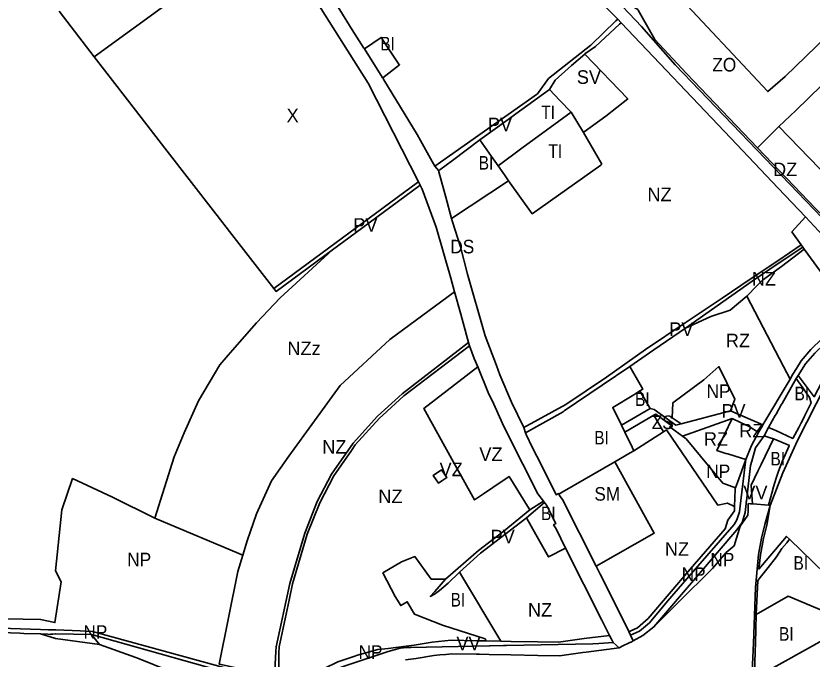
# Model space of a CAD drawing. Extents: x -650451 to -642268, y -1075216 to -1066610.
# Drawn here: x -647439 to -646558, y -1073034 to -1072322 of the extents above; entities that cross this region are included whole.
import ezdxf

# ---------------------------------------------------------------- set-up
doc = ezdxf.new("R2010")
doc.units = 0
doc.header["$LTSCALE"] = 6
doc.layers.add('1', color=7, linetype='Continuous', lineweight=35)
doc.layers.add('2', color=7, linetype='Continuous')
doc.layers.add('3', color=7, linetype='Continuous')

msp = doc.modelspace()

# ---------------------------------------------------------------- linework, layer by layer
at = {"layer": '1'}
for p, q in [((-647351.86, -1072367.52), (-647265.794, -1072304.439)), ((-647351.86, -1072367.52), (-647390.58, -1072316.75)), ((-646772.7, -1072325.66), (-646768.87, -1072329.6)), ((-646810.77, -1072451.09), (-646824.42, -1072428.58)), ((-646970.58, -1072493.62), (-646975.12, -1072488.48)), ((-646893.64, -1072504.45), (-646956.61, -1072546.07)), ((-646993.05, -1072505.68), (-646991.24, -1072509.24)), ((-646493.229, -1072622.74), (-646564.91, -1072544.37)), ((-646569.69, -1072575.19), (-646567.89, -1072577.87)), ((-646566.49, -1072579.96), (-646567.89, -1072577.87)), ((-646937.98, -1072683.25), (-646936.6, -1072687.07)), ((-646612.11, -1072774.56), (-646581.92, -1072723.91)), ((-646575.17, -1072723.31), (-646573.04, -1072719.85)), ((-646647.93, -1072759.01), (-646702.45, -1072773.39)), ((-646612.11, -1072774.56), (-646647.93, -1072759.01)), ((-646646.12, -1072767.32), (-646701.12, -1072787.08)), ((-646876.53, -1072777.33), (-646874.79, -1072783.28)), ((-646768.74, -1072774.78), (-646765, -1072782.52)), ((-646873.71, -1072877.54), (-646853.76, -1072860.47)), ((-646603.99, -1072863.84), (-646606.09, -1072863.23)), ((-646947.88, -1072937.51), (-646902.136, -1073013.834)), ((-647346.22, -1073017.52), (-647354.76, -1073006.65)), ((-646918.156, -1073013.511), (-646902.136, -1073013.834))]:
    msp.add_line(p, q, dxfattribs=at)
for points in [[(-646518.208, -1072321.92), (-646587.666, -1072389.082), (-646606.848, -1072405.785), (-646712.634, -1072292.59), (-646555.051, -1072174.933)], [(-646772.7, -1072325.66), (-646800.24, -1072297.4), (-646825.7, -1072283.54), (-646836.27, -1072271.9), (-646847.85, -1072247.99), (-646866.7, -1072227.81), (-646875, -1072218.53), (-646884.58, -1072207.83), (-646896.524, -1072194.888)], [(-646882.135, -1072193.308), (-646874.21, -1072201.34), (-646837.4, -1072236.27), (-646814.33, -1072251.34), (-646806.14, -1072261.22), (-646794.77, -1072282.59), (-646746.37, -1072333.94), (-646709.19, -1072376.06), (-646555.4, -1072536.38), (-646499.98, -1072594.11), (-646469.93, -1072603.28), (-646479.13, -1072616.26), (-646470.33, -1072617.33), (-646466.84, -1072620.18)], [(-646875.509, -1072192.58), (-646870.21, -1072199.51), (-646833.75, -1072233.32), (-646803.98, -1072254.74), (-646791.59, -1072279.78), (-646769.24, -1072303.65), (-646750.58, -1072315.02), (-646750.12, -1072315.82), (-646731.82, -1072348.2), (-646696.83, -1072385.81), (-646618.158, -1072468.098)], [(-647109.813, -1072268.588), (-647080.27, -1072315.34), (-647066.38, -1072337.31), (-647053.45, -1072357.77), (-647052.94, -1072358.64)], [(-647123.774, -1072277.899), (-647048.91, -1072396.46), (-646993.05, -1072505.68)], [(-646772.7, -1072325.66), (-646774.73, -1072327.6), (-646802.59, -1072354.28), (-646849.19, -1072391.28), (-646861.68, -1072408.1), (-646910.02, -1072442.61), (-646975.12, -1072488.48)], [(-646768.87, -1072329.6), (-646770.77, -1072331.34), (-646797.51, -1072355.77), (-646809.18, -1072364.18), (-646809.315, -1072364.299)], [(-646564.91, -1072544.37), (-646595.21, -1072512.47), (-646647.48, -1072457.43), (-646768.87, -1072329.6)], [(-647052.94, -1072358.64), (-647034.39, -1072345.9), (-647027.28, -1072356.56), (-647022.12, -1072364.32), (-647014.73, -1072375.41), (-647014.14, -1072376.08), (-647032.76, -1072390.75)], [(-647052.94, -1072358.64), (-647035.2, -1072386.94), (-647033.83, -1072389.07), (-647033.19, -1072390.06), (-647032.76, -1072390.75)], [(-646504.244, -1072357.026), (-646575.792, -1072426.789), (-646594.561, -1072444.38)], [(-647153.2, -1072623.68), (-647202.22, -1072560.47), (-647215.71, -1072543.07), (-647217.32, -1072540.99), (-647273.75, -1072468.22), (-647306.23, -1072426.35), (-647351.86, -1072367.52)], [(-646848.37, -1072403.6), (-646841.82, -1072393.03), (-646827.49, -1072380.37), (-646823.75, -1072377.06), (-646809.315, -1072364.299)], [(-646809.315, -1072364.299), (-646761.676, -1072413.971), (-646785.86, -1072433.01), (-646809.96, -1072450.5), (-646810.77, -1072451.09)], [(-647032.76, -1072390.75), (-647031.38, -1072392.97), (-646994.61, -1072453.36), (-646978.14, -1072483.05), (-646975.12, -1072488.48)], [(-646848.37, -1072403.6), (-646885.4, -1072430.37), (-646893.97, -1072436.54), (-646925.22, -1072459.03)], [(-646848.37, -1072403.6), (-646836.67, -1072415.8), (-646824.42, -1072428.58)], [(-646824.42, -1072428.58), (-646878.91, -1072468.54), (-646905.18, -1072487.8)], [(-646893.64, -1072504.45), (-646867.283, -1072540.984), (-646791.569, -1072487.198), (-646790.354, -1072486.136), (-646810.77, -1072451.09)], [(-646594.561, -1072444.38), (-646594.606, -1072444.422), (-646618.158, -1072468.098)], [(-646345.741, -1072460.38), (-646389.081, -1072507.297), (-646445.877, -1072566.771), (-646459.575, -1072583.748), (-646594.561, -1072444.38)], [(-646970.58, -1072493.62), (-646969.66, -1072492.47), (-646955.66, -1072482.12), (-646925.22, -1072459.03)], [(-646905.18, -1072487.8), (-646912.22, -1072477.69), (-646925.22, -1072459.03)], [(-646464.22, -1072595.84), (-646496.37, -1072590.65), (-646554.1, -1072535.1), (-646618.158, -1072468.098)], [(-646970.58, -1072493.62), (-646970.68, -1072494.71), (-646962.95, -1072522.46), (-646956.61, -1072546.07)], [(-646905.18, -1072487.8), (-646898.1, -1072498.02), (-646893.64, -1072504.45)], [(-647153.2, -1072623.68), (-646994.2, -1072506.52), (-646993.05, -1072505.68)], [(-646991.24, -1072509.24), (-647063.38, -1072562.42), (-647088.4, -1072580.868)], [(-646953.2, -1072627.45), (-646957.5, -1072612.09), (-646973.68, -1072555.68), (-646989.01, -1072513.62), (-646991.24, -1072509.24)], [(-646956.61, -1072546.07), (-646955.57, -1072549.93), (-646946.68, -1072577.5), (-646939.01, -1072607.91), (-646920.3, -1072673.54), (-646919.57, -1072676.08), (-646907.04, -1072708.96), (-646903.17, -1072719.13), (-646890.36, -1072749.26), (-646876.53, -1072777.33)], [(-646569.69, -1072575.19), (-646580.06, -1072561.09), (-646564.91, -1072544.37)], [(-646876.53, -1072777.33), (-646830.21, -1072751.9), (-646785.3, -1072721.58), (-646742.12, -1072691.26), (-646698.27, -1072661.58), (-646657.13, -1072634.3), (-646626.37, -1072613.4), (-646595.77, -1072593.16), (-646569.69, -1072575.19)], [(-647284.75, -1072877.79), (-647263.58, -1072809.97), (-647252.29, -1072783.24), (-647236.54, -1072748.09), (-647212.92, -1072708.05), (-647198.77, -1072691.71), (-647172.36, -1072661.69), (-647146.21, -1072634.02), (-647088.4, -1072580.868)], [(-647088.4, -1072580.868), (-647150.75, -1072626.84), (-647153.2, -1072623.68)], [(-646567.89, -1072577.87), (-646594.18, -1072595.26), (-646623.97, -1072615.59), (-646697.89, -1072667.65)], [(-646629.86, -1072632.07), (-646618.94, -1072620.88), (-646612.66, -1072614.57), (-646591.49, -1072599.19), (-646566.49, -1072579.96)], [(-646566.49, -1072579.96), (-646534.36, -1072624), (-646531.13, -1072626.73), (-646513.209, -1072641.935)], [(-647187.445, -1072918.804), (-647182.61, -1072902.92), (-647172.48, -1072872.92), (-647155.72, -1072836.46), (-647136.69, -1072808.98), (-647079.74, -1072731.1), (-647025.04, -1072679.96), (-646953.2, -1072627.45)], [(-646937.98, -1072683.25), (-646943.62, -1072661.69), (-646946.31, -1072652.08), (-646953.2, -1072627.45)], [(-646629.86, -1072632.07), (-646648.27, -1072647.48), (-646669.6, -1072654.53), (-646697.89, -1072667.65)], [(-646629.86, -1072632.07), (-646589.37, -1072709.83), (-646581.92, -1072723.91)], [(-646486.95, -1072644.87), (-646523.5, -1072692.86), (-646553.12, -1072751.12), (-646573.72, -1072791.74), (-646590.21, -1072827.45), (-646603.99, -1072863.84)], [(-646581.92, -1072723.91), (-646578.98, -1072718.36), (-646575.12, -1072712.2), (-646569.81, -1072703.71), (-646558.97, -1072691.01), (-646534.18, -1072666.63), (-646517.19, -1072650.7), (-646512.21, -1072646.18), (-646511.84, -1072645.84), (-646510.28, -1072644.42)], [(-646573.04, -1072719.85), (-646565.04, -1072706.87), (-646554.85, -1072695.37), (-646544.26, -1072685.38), (-646538.05, -1072679.53), (-646531.95, -1072673.77), (-646519.93, -1072662.47)], [(-646697.89, -1072667.65), (-646732.95, -1072691.68), (-646759.491, -1072709.878)], [(-646573.04, -1072719.85), (-646555.29, -1072743.47), (-646527.32, -1072689.94), (-646522.77, -1072683), (-646513.05, -1072668.97)], [(-647152.621, -1073052.925), (-647150.83, -1073025.11), (-647150.52, -1073020.25), (-647135.42, -1072949.98), (-647118.99, -1072894.49), (-647105.33, -1072859.4), (-647089.44, -1072829.16), (-647065.33, -1072794.77), (-647038.45, -1072764.87), (-647011.27, -1072740.1), (-646937.98, -1072683.25)], [(-646936.6, -1072687.07), (-647009.34, -1072742.3), (-647032.7, -1072763.68), (-647036.29, -1072766.96), (-647063.04, -1072796.74), (-647067.22, -1072802.77), (-647086.65, -1072830.76), (-647102.38, -1072860.7), (-647116.33, -1072895.3), (-647132.47, -1072950.4), (-647136.39, -1072968.63), (-647147.48, -1073020.28), (-647147.55, -1073026.8), (-647147.6, -1073031.71), (-647147.85, -1073054.204)], [(-646936.6, -1072687.07), (-646931.52, -1072701.11), (-646927.67, -1072710.45)], [(-646869.88, -1072868.45), (-646870.73, -1072867.3), (-646893, -1072831.51), (-646910.92, -1072843.76), (-646921.07, -1072850.69), (-646931.1, -1072857.55), (-646954.51, -1072815.63), (-646987.154, -1072756.377), (-646927.67, -1072710.45)], [(-646854.98, -1072858.89), (-646861.08, -1072851.02), (-646877.79, -1072818.08), (-646892.15, -1072789.78), (-646900.09, -1072772.84), (-646909.9, -1072751.79), (-646916.01, -1072738.71), (-646927.67, -1072710.45)], [(-646759.491, -1072709.878), (-646789.83, -1072730.68), (-646831.91, -1072759.13), (-646833.27, -1072760.04), (-646874.79, -1072783.28)], [(-646759.491, -1072709.878), (-646747.87, -1072729.85), (-646744.94, -1072734.88), (-646748.3, -1072737.01)], [(-646647.93, -1072759.01), (-646643.36, -1072746.04), (-646660.89, -1072709.97), (-646677.39, -1072724.85), (-646711.79, -1072750.02), (-646712.46, -1072766.76), (-646702.45, -1072773.39)], [(-646575.17, -1072723.31), (-646572.64, -1072726.97), (-646570.64, -1072729.84), (-646560.74, -1072744.12), (-646558.8, -1072750.3), (-646566, -1072764.9), (-646567.66, -1072768.09), (-646569.72, -1072772.24), (-646572.45, -1072777.28), (-646579.08, -1072789.5), (-646598.02, -1072780.93), (-646599.75, -1072780.14), (-646605.93, -1072777.31)], [(-646575.17, -1072723.31), (-646590.83, -1072750.81), (-646591.82, -1072752.54), (-646597.52, -1072762.54), (-646598.51, -1072764.27), (-646601.72, -1072769.92), (-646605.93, -1072777.31)], [(-646768.74, -1072774.78), (-646778.2, -1072755.19), (-646755.1, -1072741.28), (-646748.3, -1072737.01)], [(-646748.3, -1072737.01), (-646737.05, -1072756.4), (-646768.74, -1072774.78)], [(-646702.45, -1072773.39), (-646708.65, -1072775.02), (-646732.5, -1072757.63), (-646737.05, -1072756.4)], [(-646754.96, -1072803.29), (-646722.072, -1072782.236), (-646732.76, -1072763.81), (-646765, -1072782.52)], [(-646732.76, -1072763.81), (-646730.73, -1072762.64), (-646712.35, -1072776), (-646715.23, -1072776.76), (-646709.14, -1072781.21), (-646701.12, -1072787.08)], [(-646631.08, -1072812.68), (-646643.01, -1072809.08), (-646651.11, -1072806.64), (-646653.02, -1072806.07), (-646663.07, -1072803.04), (-646646.12, -1072767.32)], [(-646646.12, -1072767.32), (-646636.84, -1072771.74), (-646627.38, -1072776.23), (-646616.97, -1072782.9)], [(-646616.97, -1072782.9), (-646616.6, -1072782.31), (-646612.76, -1072775.67), (-646612.4, -1072775.05), (-646612.11, -1072774.56)], [(-646610.86, -1072786.74), (-646606.795, -1072778.965), (-646606.54, -1072778.47), (-646605.93, -1072777.31)], [(-646874.79, -1072783.28), (-646874.23, -1072785.2), (-646866.86, -1072800.03), (-646857.61, -1072818.4), (-646840.87, -1072851.94), (-646838.22, -1072850.53), (-646837.81, -1072851.3)], [(-646765, -1072782.52), (-646756.92, -1072799.26), (-646754.96, -1072803.29)], [(-646732.95, -1072998.07), (-646684.36, -1072941.43), (-646640.96, -1072890.83), (-646635.11, -1072882.47), (-646631.89, -1072871.33), (-646630.76, -1072861.61), (-646630.57, -1072859.99), (-646630.45, -1072858.93), (-646625.91, -1072819.66), (-646624.54, -1072814.52), (-646620.27, -1072799.95), (-646610.86, -1072786.74)], [(-646722.072, -1072782.236), (-646722.07, -1072782.24), (-646718.72, -1072780.09), (-646662.12, -1072863.28), (-646651.42, -1072861.1), (-646643.445, -1072864.732)], [(-646631.08, -1072812.68), (-646624.81, -1072797.42), (-646616.97, -1072782.9)], [(-646600.37, -1072790.04), (-646603.99, -1072788.9), (-646610.86, -1072786.74)], [(-646642.404, -1072844.195), (-646656.36, -1072839.08), (-646697.09, -1072790.03), (-646701.12, -1072787.08)], [(-646623.67, -1072862.03), (-646623.71, -1072861.37), (-646623.95, -1072857.6), (-646625.02, -1072841.21), (-646617.596, -1072825.798), (-646614.07, -1072818.47), (-646600.37, -1072790.04)], [(-646600.37, -1072790.04), (-646599.44, -1072790.33), (-646582.77, -1072797.45), (-646582.98, -1072797.91), (-646590.47, -1072814.45), (-646594.89, -1072825.68), (-646597.38, -1072833.61), (-646600.35, -1072843.05), (-646602.37, -1072849.93), (-646605.32, -1072860.63), (-646606.09, -1072863.23)], [(-646754.96, -1072803.29), (-646758.9, -1072805.56), (-646775.85, -1072815.39)], [(-646631.08, -1072812.68), (-646631.85, -1072818.45), (-646637.52, -1072867.43), (-646637.92, -1072870.91), (-646640.92, -1072879.6), (-646644.12, -1072884.84), (-646689.13, -1072936.62), (-646717.7, -1072969.5), (-646737.7, -1072993.52), (-646748.51, -1073002.74), (-646758.44, -1073007.19)], [(-646631.08, -1072812.68), (-646640.313, -1072838.394), (-646642.404, -1072844.195)], [(-646775.85, -1072815.39), (-646834.08, -1072849.15), (-646837.81, -1072851.3)], [(-646775.85, -1072815.39), (-646732.28, -1072894.29), (-646796.68, -1072930.92)], [(-648023.818, -1072955.949), (-648023.495, -1072955.875), (-647811.752, -1072979.4), (-647778.296, -1072982.767), (-647411.293, -1072989.813), (-647395.47, -1072993.25), (-647388.62, -1072948.03), (-647394.87, -1072936.08), (-647387.64, -1072868.69), (-647375.92, -1072833.99), (-647331.82, -1072854.49), (-647284.75, -1072877.79)], [(-646642.404, -1072844.195), (-646642.39, -1072844.2), (-646642.438, -1072844.29), (-646642.939, -1072845.68), (-646643.445, -1072864.732)], [(-646837.81, -1072851.3), (-646836.5, -1072853.76), (-646833.67, -1072857.15), (-646796.68, -1072930.92)], [(-646853.76, -1072860.47), (-646854.98, -1072858.89), (-646869.88, -1072868.45)], [(-646853.76, -1072860.47), (-646851.49, -1072863.39), (-646841.08, -1072883.58), (-646843.77, -1072885.18), (-646840.69, -1072889.58), (-646830.67, -1072911.13)], [(-646760.416, -1073003.25), (-646758.883, -1073002.885), (-646751.061, -1072999.106), (-646739.241, -1072988.798), (-646692.432, -1072934.135), (-646653.846, -1072889.44), (-646650.798, -1072879.828), (-646643.574, -1072869.57), (-646643.445, -1072864.732)], [(-646732.95, -1072998.07), (-646710.3, -1072975.31), (-646693.9, -1072958.84), (-646680.07, -1072945.74), (-646668.09, -1072933.43), (-646652.76, -1072915.66), (-646644.069, -1072908.218), (-646644.059, -1072908.208), (-646637.2, -1072886.57), (-646628.7, -1072874.5), (-646628.58, -1072869.88), (-646628.36, -1072861.71), (-646625.96, -1072861.88), (-646624.824, -1072861.951), (-646623.67, -1072862.03)], [(-646618.56, -1073101.42), (-646620.19, -1073102.14), (-646621.38, -1073102.66), (-646627, -1073073.75), (-646626.07, -1073068.71), (-646624.17, -1073058.44), (-646623.51, -1073039.8), (-646622.66, -1073016.13), (-646620.39, -1072954.3), (-646616.9, -1072917.9), (-646613.68, -1072899.89), (-646610.04, -1072884.81), (-646603.99, -1072863.84)], [(-646606.09, -1072863.23), (-646623.25, -1072862.05), (-646623.67, -1072862.03)], [(-646603.99, -1072863.84), (-646607.94, -1072885.41), (-646611.51, -1072900.28), (-646614.73, -1072918.29), (-646616.49, -1072934), (-646586.22, -1072897.88), (-646582.8, -1072901.17)], [(-646963.13, -1072945.34), (-646926.89, -1072913.53), (-646898.25, -1072891.9), (-646869.88, -1072868.45)], [(-647187.445, -1072918.804), (-647282.31, -1072878.82), (-647284.75, -1072877.79)], [(-646947.88, -1072937.51), (-646924.47, -1072916.56), (-646875.38, -1072878.83), (-646873.71, -1072877.54)], [(-646830.67, -1072911.13), (-646849.28, -1072920.67), (-646863.45, -1072895.67), (-646873.71, -1072877.54)], [(-646582.8, -1072901.17), (-646585.85, -1072904.89), (-646591.2, -1072911.41), (-646596.98, -1072920.49), (-646606.48, -1072932.39), (-646613.84, -1072941.71), (-646617.93, -1072946.87), (-646619.48, -1072984.34)], [(-646582.8, -1072901.17), (-646530.4, -1072951.72), (-646514.85, -1072956.93)], [(-647152.621, -1073052.925), (-647154.999, -1073052.287), (-647213.218, -1073039.42), (-647213.562, -1073039.322), (-647192.93, -1072936.82), (-647187.445, -1072918.804)], [(-646781.703, -1073007.452), (-646790.32, -1072990.53), (-646830.67, -1072911.13)], [(-646918.156, -1073013.511), (-646919.54, -1073011.41), (-646966.57, -1072996.25), (-646997.71, -1072983.89), (-647005.6, -1072970.29), (-647012.79, -1072974.53), (-647018.82, -1072964.39), (-647032.61, -1072938.39), (-647011.86, -1072926.17), (-646997.15, -1072920.28), (-646979.1, -1072945.1), (-646963.13, -1072945.34)], [(-646796.68, -1072930.92), (-646792.2, -1072939.86), (-646766.51, -1072991.1), (-646760.416, -1073003.25)], [(-646963.13, -1072945.34), (-646975.15, -1072958.74), (-646980.18, -1072964.34), (-646975.29, -1072961.95), (-646969.93, -1072957.88), (-646960.29, -1072949.77), (-646947.88, -1072937.51)], [(-647153.44, -1073058.06), (-647213.99, -1073041.449), (-647353.78, -1073003.1), (-647367.45, -1073002.47), (-647394.46, -1073001.23), (-647400.55, -1073001.48), (-647402.49, -1073001.41), (-647411.324, -1073001.08), (-647444.42, -1072999.87), (-647497.35, -1072997.93), (-647682.74, -1072990.95), (-647686.14, -1072990.78), (-647778.3, -1072986.29), (-647790.52, -1072985.06), (-647846.85, -1072979.37), (-648014.16, -1072961.36), (-648023.37, -1072960.37)], [(-646531.46, -1072970.12), (-646544.68, -1072980.62), (-646584.23, -1072964.22), (-646619.48, -1072984.34)], [(-646516.7, -1072996.65), (-646616.55, -1073052.21), (-646621.44, -1073049.79), (-646620.71, -1073025.49), (-646620.38, -1073015.9), (-646619.48, -1072984.34)], [(-647689.11, -1072996.49), (-647685.75, -1072996.6), (-647683.21, -1072996.68), (-647547.02, -1073001.04), (-647497.2, -1073002.63), (-647485.29, -1073003.08), (-647434.2, -1073005.02), (-647429.65, -1073005.19), (-647411.34, -1073005.89)], [(-646755.58, -1073013.43), (-646744.92, -1073007.46), (-646732.95, -1072998.07)], [(-647354.76, -1073006.65), (-647394.59, -1073005.58), (-647395.08, -1073005.64), (-647397.74, -1073005.95), (-647400.27, -1073006.24), (-647400.76, -1073006.29), (-647403.05, -1073006.2), (-647411.34, -1073005.89)], [(-647411.34, -1073005.89), (-647394.782, -1073011.002), (-647346.22, -1073017.52)], [(-647154.77, -1073062.68), (-647168.06, -1073058.96), (-647214.91, -1073045.83), (-647354.76, -1073006.65)], [(-646760.416, -1073003.25), (-646758.44, -1073007.19), (-646755.58, -1073013.43)], [(-646918.156, -1073013.511), (-646928.807, -1073013.313), (-646956.919, -1073012.775), (-646978.077, -1073014.931), (-646997.824, -1073018.092), (-647006.715, -1073019.236), (-647026.763, -1073021.811), (-647037.971, -1073023.24), (-647060.677, -1073029.351), (-647064.784, -1073030.747), (-647082.267, -1073036.684), (-647097.466, -1073044.268), (-647118.513, -1073051.327), (-647134.596, -1073054.974), (-647143.312, -1073055.421), (-647147.85, -1073054.204)], [(-647147.43, -1073059.78), (-647147.17, -1073059.97), (-647134.03, -1073059.94), (-647118.27, -1073055.88), (-647033.44, -1073027.43), (-647028.91, -1073025.91), (-647026.54, -1073025.11), (-647013.4, -1073021.42), (-647006.15, -1073020.99), (-647001.66, -1073020.72), (-646914.54, -1073019), (-646913.94, -1073018.99), (-646899.22, -1073018.7), (-646895.76, -1073018.63), (-646800.44, -1073016.74), (-646793.8, -1073016.61), (-646777.74, -1073015.29)], [(-646781.703, -1073007.452), (-646809.778, -1073011.019), (-646838.25, -1073014.938), (-646861.07, -1073014.672), (-646890.523, -1073014.073), (-646902.136, -1073013.834)], [(-646781.703, -1073007.452), (-646779.55, -1073011.68), (-646777.74, -1073015.29)], [(-646755.58, -1073013.43), (-646758.04, -1073014.78), (-646758.6, -1073015.08), (-646759.05, -1073015.3), (-646759.32, -1073015.43), (-646768.65, -1073019.89), (-646769.1, -1073020.1), (-646769.55, -1073020.32), (-646771.21, -1073021.24), (-646777.74, -1073015.29)], [(-647154.77, -1073062.68), (-647218.06, -1073062.37), (-647247.46, -1073055.63), (-647263.8, -1073049), (-647297.53, -1073035.3), (-647305.94, -1073031.89), (-647346.22, -1073017.52)], [(-646771.21, -1073021.24), (-646807.81, -1073025.89), (-646811.37, -1073026.34), (-646837.31, -1073029.95), (-646861.31, -1073029.67), (-646890.83, -1073029.07), (-646915.09, -1073028.57), (-646925.53, -1073028.38), (-646929.09, -1073028.31), (-646956.3, -1073027.79), (-646962.9, -1073028.46), (-646969.52, -1073029.14), (-646976.13, -1073029.81), (-646982.65, -1073030.85), (-646989.16, -1073031.9), (-646995.68, -1073032.94), (-647007.49, -1073034.46)]]:
    msp.add_lwpolyline(points, dxfattribs=at)
msp.add_lwpolyline([(-646967.466, -1072836.573), (-646971.04, -1072838.99), (-646976.8, -1072830.5), (-646967.71, -1072824.33), (-646961.93, -1072832.83)], close=True, dxfattribs=at)

# ---------------------------------------------------------------- texts
at = {"layer": '2'}
for s, width, p in [('BI', 0.85, (-647035.409, -1072360.228)), ('TI', 0.85, (-646857.3, -1072436.25)), ('BI', 0.85, (-646926.5, -1072492.104)), ('DS', 0.95, (-646957.955, -1072584.793)), ('NP', 0.95, (-646674.403, -1072744.79)), ('BI', 0.85, (-646577.177, -1072747.337)), ('BI', 0.85, (-646798.699, -1072796.234)), ('BI', 0.85, (-646603.761, -1072819.478)), ('NP', 0.95, (-646674.772, -1072833.456)), ('BI', 0.85, (-646857.599, -1072879.954)), ('BI', 0.85, (-646578.289, -1072934.778)), ('BI', 0.85, (-646957.617, -1072975.527))]:
    msp.add_text(s, height=15, dxfattribs=dict(at, width=width)).set_placement(p)
for s, p in [('SV', (-646818, -1072397.23)), ('X', (-647139.098, -1072439.752)), ('PV', (-646916.395, -1072449.721)), ('DZ', (-646600.938, -1072499.368)), ('NZ', (-646739.832, -1072527.077)), ('PV', (-647065.311, -1072560.841)), ('NZ', (-646624.382, -1072620.363)), ('PV', (-646715.739, -1072676.131)), ('PV', (-646658.118, -1072766.546)), ('RZ', (-646638.325, -1072788.422)), ('NZ', (-647099.669, -1072806.378)), ('VZ', (-646925.856, -1072814.544)), ('VZ', (-646969.856, -1072831.31)), ('NZ', (-647037.602, -1072861.056)), ('VV', (-646633.804, -1072856.8)), ('PV', (-646913.385, -1072905.643)), ('NZ', (-646720.621, -1072919.427)), ('NZ', (-646872.092, -1072986.666)), ('VV', (-646951.185, -1073023.92))]:
    msp.add_text(s, height=15, dxfattribs=at).set_placement(p)
at = {"layer": '3'}
for s, width, p in [('ZO', 0.95, (-646668.121, -1072383.549)), ('TI', 0.85, (-646849.405, -1072479.126)), ('BI', 0.85, (-646753.541, -1072753.612)), ('ZS', 0.95, (-646735.21, -1072779.166)), ('SM', 0.95, (-646798.601, -1072858.395)), ('NP', 0.95, (-647315.377, -1072931.039)), ('NP', 0.95, (-646670.251, -1072931.141)), ('NP', 0.95, (-646701.944, -1072947.266)), ('NP', 0.95, (-647363.845, -1073011.199)), ('BI', 0.85, (-646594.204, -1073013.309)), ('NP', 0.95, (-647059.423, -1073033.404))]:
    msp.add_text(s, height=15, dxfattribs=dict(at, width=width)).set_placement(p)
for s, p in [('RZ', (-646653.133, -1072688.724)), ('NZz', (-647138.229, -1072697.414)), ('RZ', (-646677.438, -1072797.683))]:
    msp.add_text(s, height=15, dxfattribs=at).set_placement(p)

doc.saveas('drawing.dxf')
